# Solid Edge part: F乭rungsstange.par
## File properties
Username: bmolnar
Dokumentum tartalom típus: 0
Author: bmolnar
Last saved by: bmolnar
Revision: 91
Sűrűség: 0,000 kg/m^3
Pontosság: 0,990
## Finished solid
Body 1: solid body, 8 faces, 7 edges, 1 vertex.
  Faces by surface: cone 4, cylinder 2, plane 2
  Edges by curve: circle 7
Bounding box of the edges (mm): 5.000 x 5.000 x 223.000, from (-2.5, -2.5, -14) to (2.5, 2.5, 209).
Cylindrical faces by radius (mm): R1.2295 x1, R2.5 x1
Conical faces (half-angle, radius in mm at the cone's reference point): 45 deg R1.3295 x1, 45 deg R2.25 x1, 45 deg R2.4 x1, 59 deg R0.6148 x1
Planar faces by outward normal: +z 1, -z 1
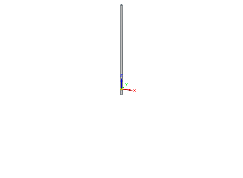
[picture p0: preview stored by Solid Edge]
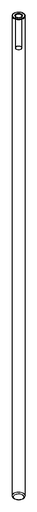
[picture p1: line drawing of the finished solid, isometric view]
